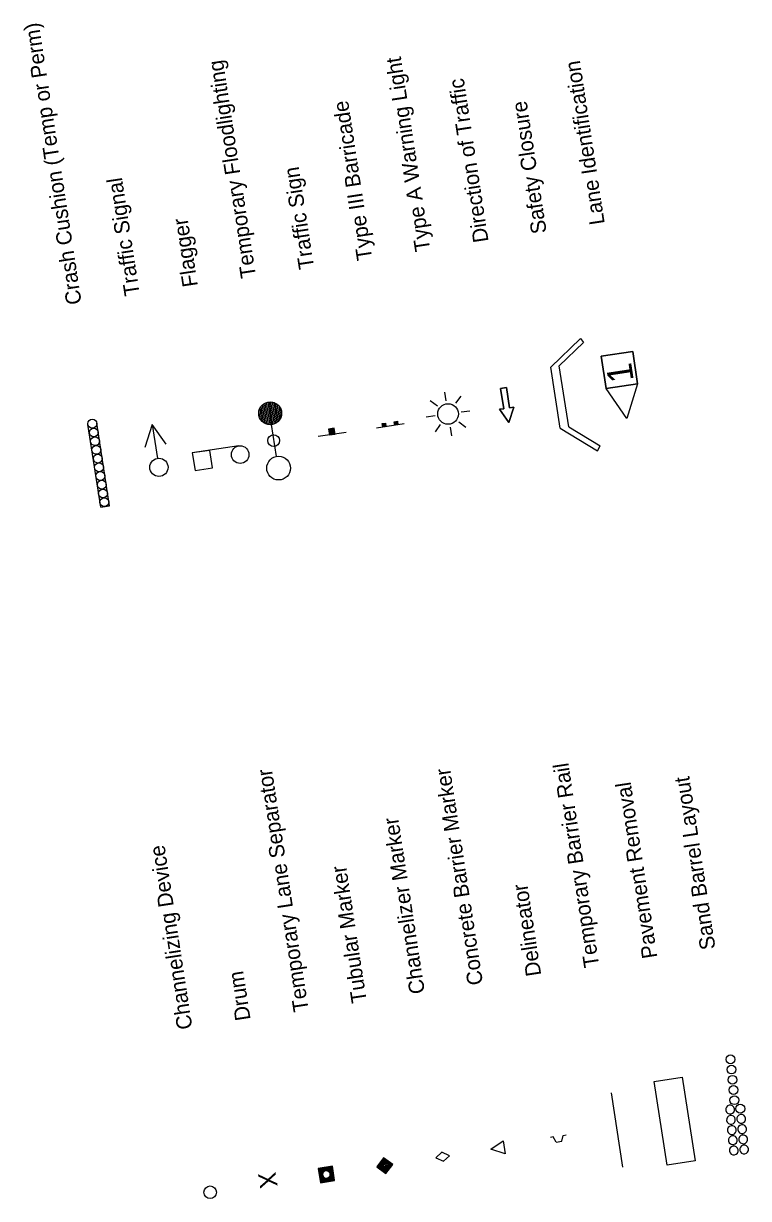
# Model space of a CAD drawing. Extents: x 5190448 to 5202667, y 3698220 to 3717523.
# Drawn here: x 5202051 to 5202667, y 3698220 to 3699220 of the extents above; entities that cross this region are included whole.
import ezdxf

# ---------------------------------------------------------------- set-up
doc = ezdxf.new("R2010")
doc.units = 0
for name, color, linetype in [('Default', 7, 'Continuous'), ('dsnCurbBack', 7, 'Continuous'), ('dsnCurbFace', 7, 'Continuous'), ('dsnIntersectionGJSLine', 7, 'Continuous'), ('dsnLaneLine', 7, 'Continuous'), ('dsnSawCutLine', 7, 'Continuous'), ('dsnShadingSpecial', 7, 'Continuous'), ('dsnShoulderPaved', 7, 'Continuous')]:
    doc.layers.add(name, color=color, linetype=linetype)

msp = doc.modelspace()

# ---------------------------------------------------------------- linework, layer by layer
at = {"layer": 'Default'}
for p, q in [((5202568.7, 3698940.8), (5202542, 3698936.8)), ((5202572.9, 3698913.3), (5202568.7, 3698940.8)), ((5202568.7, 3698940.8), (5202568.7, 3698940.8)), ((5202542, 3698936.8), (5202546.2, 3698909.3)), ((5202546.2, 3698909.3), (5202572.9, 3698913.3)), ((5202546.2, 3698909.3), (5202572.9, 3698913.3)), ((5202572.9, 3698913.3), (5202546.2, 3698909.3)), ((5202572.9, 3698913.3), (5202546.2, 3698909.3)), ((5202572.9, 3698913.3), (5202563.8, 3698883.8)), ((5202563.8, 3698883.8), (5202546.2, 3698909.3))]:
    msp.add_line(p, q, dxfattribs=at)
msp.add_lwpolyline([(5202546.2, 3698909.3), (5202542, 3698936.8), (5202568.7, 3698940.8), (5202572.9, 3698913.3)], dxfattribs=at)
at = {"layer": 'dsnCurbFace'}
for p, q in [((5202410, 3698898.7), (5202408.9, 3698906.1)), ((5202418.4, 3698896.7), (5202422.8, 3698902.7)), ((5202402.7, 3698894.3), (5202396.6, 3698898.7)), ((5202400.6, 3698885.9), (5202393.2, 3698884.8)), ((5202420.8, 3698880.9), (5202426.8, 3698876.5)), ((5202422.8, 3698889.3), (5202430.3, 3698890.4)), ((5202160.2, 3698878.5), (5202153.9, 3698859.1)), ((5202160.2, 3698878.5), (5202164.6, 3698849.8)), ((5202172, 3698861.8), (5202160.2, 3698878.5)), ((5202405.1, 3698878.5), (5202400.6, 3698872.5)), ((5202413.4, 3698876.5), (5202414.5, 3698869.1)), ((5202233.8, 3698860.4), (5202194.2, 3698854.4))]:
    msp.add_line(p, q, dxfattribs=at)
for points in [[(5202456.4, 3698909.4), (5202461.4, 3698910.2), (5202464, 3698892.9), (5202467.7, 3698893.5), (5202463.4, 3698880.2), (5202455.4, 3698891.6), (5202459.1, 3698892.1)], [(5202194.2, 3698854.4), (5202196.5, 3698839.5), (5202211.3, 3698841.8), (5202209.1, 3698856.6)]]:
    msp.add_lwpolyline(points, close=True, dxfattribs=at)
for centre, radius in [((5202411.7, 3698887.6), 8.75), ((5202234.9, 3698853), 7.5), ((5202165.8, 3698842.2), 7.74)]:
    msp.add_circle(centre, radius, dxfattribs=at)
at = {"layer": 'dsnIntersectionGJSLine'}
msp.add_lwpolyline([(5202459.1, 3698892.1), (5202455.4, 3698891.6), (5202463.4, 3698880.2), (5202467.7, 3698893.5), (5202464, 3698892.9), (5202461.4, 3698910.2), (5202456.4, 3698909.4), (5202459.1, 3698892.1)], dxfattribs=at)
at = {"layer": 'dsnLaneLine'}
for p, q in [((5202365.9, 3698880.8), (5202368.6, 3698881.2)), ((5202368.7, 3698881), (5202365.9, 3698880.6)), ((5202365.9, 3698880.5), (5202368.7, 3698880.9)), ((5202116.3, 3698808.3), (5202105.5, 3698878.7)), ((5202123.7, 3698809.4), (5202112.9, 3698879.8)), ((5202261.4, 3698878.5), (5202265.5, 3698851.4)), ((5202325, 3698871.9), (5202301.3, 3698868.3)), ((5202314.9, 3698875), (5202310.1, 3698874.3)), ((5202310.2, 3698874), (5202315, 3698874.8)), ((5202315, 3698874.6), (5202310.2, 3698873.8)), ((5202310.2, 3698873.6), (5202315.1, 3698874.3)), ((5202315.1, 3698874.1), (5202310.3, 3698873.4)), ((5202310.3, 3698873), (5202315.1, 3698873.7)), ((5202315.2, 3698873.6), (5202310.3, 3698872.8)), ((5202310.4, 3698872.4), (5202315.2, 3698873.2)), ((5202315.3, 3698872.9), (5202310.5, 3698872.1)), ((5202310.5, 3698871.8), (5202315.3, 3698872.6)), ((5202315.3, 3698872.4), (5202310.5, 3698871.7)), ((5202310.6, 3698871.4), (5202315.4, 3698872.2)), ((5202315.4, 3698871.9), (5202310.6, 3698871.1)), ((5202310.6, 3698871), (5202315.5, 3698871.7)), ((5202315.5, 3698871.5), (5202310.7, 3698870.8)), ((5202310.7, 3698870.5), (5202315.5, 3698871.3)), ((5202315.6, 3698871), (5202310.7, 3698870.3)), ((5202310.8, 3698870.1), (5202315.6, 3698870.8)), ((5202350.8, 3698875.8), (5202374.5, 3698879.4)), ((5202355.7, 3698879.2), (5202358.5, 3698879.6)), ((5202358.5, 3698879.5), (5202355.7, 3698879.1)), ((5202355.8, 3698878.9), (5202358.5, 3698879.4)), ((5202358.5, 3698879.2), (5202355.8, 3698878.8)), ((5202355.8, 3698878.7), (5202358.6, 3698879.1)), ((5202358.6, 3698878.9), (5202355.8, 3698878.5)), ((5202355.8, 3698878.4), (5202358.6, 3698878.8)), ((5202358.6, 3698878.6), (5202355.9, 3698878.1)), ((5202355.9, 3698878), (5202358.7, 3698878.4)), ((5202358.7, 3698878.2), (5202355.9, 3698877.8)), ((5202355.9, 3698877.7), (5202358.7, 3698878.1)), ((5202358.7, 3698878), (5202356, 3698877.6)), ((5202356, 3698877.4), (5202358.7, 3698877.8)), ((5202358.8, 3698877.7), (5202356, 3698877.3)), ((5202356, 3698877.2), (5202358.8, 3698877.6)), ((5202358.8, 3698877.5), (5202356, 3698877.1)), ((5202356.1, 3698876.9), (5202358.8, 3698877.3)), ((5202358.8, 3698877.2), (5202356.1, 3698876.8)), ((5202368.7, 3698880.8), (5202365.9, 3698880.3)), ((5202366, 3698880.2), (5202368.7, 3698880.7)), ((5202368.8, 3698880.4), (5202366, 3698880)), ((5202366, 3698879.9), (5202368.8, 3698880.3)), ((5202368.8, 3698880.1), (5202366, 3698879.7)), ((5202366.1, 3698879.5), (5202368.8, 3698879.9)), ((5202368.9, 3698879.8), (5202366.1, 3698879.3)), ((5202366.1, 3698879.2), (5202368.9, 3698879.7)), ((5202368.9, 3698879.5), (5202366.1, 3698879.1)), ((5202366.2, 3698878.9), (5202368.9, 3698879.4)), ((5202368.9, 3698879.3), (5202366.2, 3698878.8)), ((5202366.2, 3698878.7), (5202368.9, 3698879.2)), ((5202369, 3698879), (5202366.2, 3698878.6)), ((5202366.2, 3698878.5), (5202369, 3698878.9)), ((5202369, 3698878.8), (5202366.3, 3698878.3)), ((5202116.3, 3698808.3), (5202123.7, 3698809.4)), ((5202501.2, 3698272.2), (5202498.7, 3698271.8)), ((5202503.6, 3698267.8), (5202501.2, 3698272.2)), ((5202508.5, 3698268.6), (5202509.5, 3698273.5)), ((5202509.5, 3698273.5), (5202512, 3698273.9)), ((5202503.6, 3698267.8), (5202508.5, 3698268.6))]:
    msp.add_line(p, q, dxfattribs=at)
for points in [[(5202251.5, 3698892.1), (5202253.1, 3698881.8)], [(5202252.5, 3698893.9), (5202254.6, 3698880.4)], [(5202253.6, 3698895.2), (5202256, 3698879.6)], [(5202254.7, 3698896.1), (5202257.3, 3698879)], [(5202255.9, 3698896.8), (5202258.7, 3698878.6)], [(5202257.1, 3698897.4), (5202260, 3698878.5)], [(5202258.3, 3698897.7), (5202261.2, 3698878.5)], [(5202258.3, 3698897.7), (5202261.2, 3698878.5)], [(5202259.5, 3698897.9), (5202262.5, 3698878.7)], [(5202260.8, 3698898), (5202263.7, 3698879)], [(5202262.1, 3698897.8), (5202264.9, 3698879.6)], [(5202263.4, 3698897.5), (5202266.1, 3698880.3)], [(5202264.8, 3698896.9), (5202267.2, 3698881.2)], [(5202266.2, 3698896.1), (5202268.3, 3698882.4)], [(5202267.7, 3698894.7), (5202269.3, 3698884.1)], [(5202269.3, 3698892.2), (5202270.1, 3698887.1)], [(5202250.7, 3698888.9), (5202251.4, 3698884.6)], [(5202458.7, 3698269), (5202460.4, 3698257.8), (5202448.2, 3698261.8), (5202458.7, 3698269), (5202460.4, 3698257.8)], [(5202351.9, 3698247), (5202358.6, 3698241.8), (5202364.1, 3698248.9), (5202356.9, 3698254), (5202352.4, 3698247.3), (5202358.5, 3698242.6), (5202363.3, 3698248.8), (5202357.1, 3698253.2), (5202353.2, 3698247.4), (5202358.3, 3698243.4), (5202362.4, 3698248.8), (5202357.3, 3698252.3), (5202354.3, 3698247.6), (5202358.2, 3698244.4), (5202361.2, 3698248.6), (5202357.5, 3698251.1), (5202355.2, 3698247.7), (5202358.1, 3698245.4), (5202360, 3698248.5), (5202357.8, 3698250), (5202356.3, 3698248), (5202357.8, 3698246.5), (5202358.7, 3698248.4), (5202357.9, 3698248.8), (5202357.7, 3698247.9)], [(5202406.5, 3698259.2), (5202401.2, 3698254.5), (5202407.7, 3698251.6), (5202413, 3698256.3), (5202406.5, 3698259.2)]]:
    msp.add_lwpolyline(points, dxfattribs=at)
for points in [[(5202369, 3698878.6), (5202366.3, 3698878.2), (5202365.8, 3698881), (5202368.6, 3698881.4)], [(5202310.8, 3698869.8), (5202315.7, 3698870.5), (5202314.9, 3698875.4), (5202310.1, 3698874.6)], [(5202358.9, 3698877.1), (5202356.1, 3698876.6), (5202355.7, 3698879.4), (5202358.4, 3698879.8)], [(5202364.6, 3698248.9), (5202356.7, 3698254.6), (5202351, 3698246.8), (5202358.8, 3698241)]]:
    msp.add_lwpolyline(points, close=True, dxfattribs=at)
for centre, radius in [((5202260.4, 3698888.2), 9.75), ((5202263.4, 3698864.9), 5.04), ((5202267.6, 3698841.5), 10.1), ((5202651.9, 3698338.3), 3.75), ((5202652.7, 3698329.6), 3.75), ((5202653.6, 3698320.9), 3.75), ((5202654.4, 3698312.2), 3.75), ((5202655.2, 3698303.5), 3.75), ((5202660.2, 3698296.3), 3.75), ((5202660.2, 3698296.3), 3.75), ((5202308.3, 3698240.3), 3.3)]:
    msp.add_circle(centre, radius, dxfattribs=at)
for centre, start, end in [((5202651.5, 3698295.5), 100.2697, 280.2697), ((5202651.5, 3698295.5), 280.2697, 100.2697), ((5202661, 3698287.6), 100.2697, 280.2697), ((5202661, 3698287.6), 280.2697, 100.2697), ((5202652.3, 3698286.8), 100.2697, 280.2697), ((5202653.1, 3698278.1), 100.2697, 280.2697), ((5202652.3, 3698286.8), 280.2697, 100.2697), ((5202653.1, 3698278.1), 280.2697, 100.2697), ((5202661.8, 3698278.9), 100.2697, 280.2697), ((5202661.8, 3698278.9), 280.2697, 100.2697), ((5202653.9, 3698269.4), 100.2697, 280.2697), ((5202653.9, 3698269.4), 280.2697, 100.2697), ((5202662.6, 3698270.2), 100.2697, 280.2697), ((5202662.6, 3698270.2), 280.2697, 100.2697), ((5202654.7, 3698260.7), 100.2697, 280.2697), ((5202654.7, 3698260.7), 280.2697, 100.2697), ((5202663.4, 3698261.5), 100.2697, 280.2697), ((5202663.4, 3698261.5), 280.2697, 100.2697)]:
    msp.add_arc(centre, 3.75, start, end, dxfattribs=at)
at = {"layer": 'dsnSawCutLine'}
for p, q in [((5202597.9, 3698248.3), (5202587.1, 3698319.4)), ((5202621.7, 3698251.9), (5202597.9, 3698248.3))]:
    msp.add_line(p, q, dxfattribs=at)
msp.add_lwpolyline([(5202587.1, 3698319.4), (5202610.8, 3698323.1), (5202621.7, 3698251.9)], dxfattribs=at)
at = {"layer": 'dsnShadingSpecial'}
for p, q in [((5202499, 3698927.5), (5202524.2, 3698951.8)), ((5202524.2, 3698951.8), (5202526.9, 3698948.5)), ((5202506.3, 3698928.6), (5202526.9, 3698948.5)), ((5202506.9, 3698875.6), (5202499, 3698927.5)), ((5202514.3, 3698876.7), (5202506.3, 3698928.6)), ((5202506.9, 3698875.6), (5202538.7, 3698856.3)), ((5202514.3, 3698876.7), (5202541, 3698860.4)), ((5202538.7, 3698856.3), (5202541, 3698860.4))]:
    msp.add_line(p, q, dxfattribs=at)
for points in [[(5202315.2, 3698235.2), (5202313.4, 3698247.3), (5202301.3, 3698245.4), (5202303.1, 3698233.3), (5202315.2, 3698235.2)], [(5202315.2, 3698235.2), (5202313.4, 3698247.3), (5202301.3, 3698245.4), (5202303.1, 3698233.3), (5202315.2, 3698235.2)], [(5202315.2, 3698235.2), (5202313.4, 3698247.3), (5202301.3, 3698245.4), (5202303.1, 3698233.4), (5202315.2, 3698235.2)], [(5202315.1, 3698235.4), (5202313.3, 3698247.2), (5202301.4, 3698245.4), (5202303.2, 3698233.4), (5202315.2, 3698235.3)], [(5202315, 3698235.5), (5202313.3, 3698247.1), (5202301.4, 3698245.3), (5202303.2, 3698233.5), (5202315.2, 3698235.3)], [(5202315, 3698235.6), (5202313.2, 3698247.1), (5202301.5, 3698245.3), (5202303.3, 3698233.6), (5202315.2, 3698235.4)], [(5202314.9, 3698235.6), (5202313.2, 3698247), (5202301.6, 3698245.2), (5202303.4, 3698233.7), (5202315.1, 3698235.4)], [(5202314.8, 3698235.7), (5202313.1, 3698246.9), (5202301.7, 3698245.2), (5202303.4, 3698233.7), (5202315, 3698235.5)], [(5202314.7, 3698235.7), (5202313, 3698246.8), (5202301.7, 3698245.1), (5202303.5, 3698233.8), (5202315, 3698235.6)], [(5202314.7, 3698235.8), (5202313, 3698246.8), (5202301.8, 3698245.1), (5202303.5, 3698233.9), (5202314.9, 3698235.6)], [(5202314.6, 3698235.8), (5202312.9, 3698246.7), (5202301.9, 3698245), (5202303.6, 3698234), (5202314.8, 3698235.7)], [(5202314.5, 3698235.9), (5202312.9, 3698246.6), (5202302, 3698244.9), (5202303.6, 3698234), (5202314.7, 3698235.7)], [(5202314.4, 3698235.9), (5202312.8, 3698246.5), (5202302, 3698244.9), (5202303.7, 3698234.1), (5202314.7, 3698235.8)], [(5202314.4, 3698236), (5202312.8, 3698246.5), (5202302.1, 3698244.8), (5202303.7, 3698234.2), (5202314.6, 3698235.8)], [(5202314.3, 3698236.1), (5202312.7, 3698246.4), (5202302.2, 3698244.8), (5202303.8, 3698234.3), (5202314.5, 3698235.9)], [(5202314.2, 3698236.1), (5202312.7, 3698246.3), (5202302.3, 3698244.7), (5202303.9, 3698234.3), (5202314.4, 3698235.9)], [(5202314.1, 3698236.2), (5202312.6, 3698246.2), (5202302.3, 3698244.7), (5202303.9, 3698234.4), (5202314.4, 3698236)], [(5202314.1, 3698236.2), (5202312.5, 3698246.2), (5202302.4, 3698244.6), (5202304, 3698234.5), (5202314.3, 3698236.1)], [(5202314, 3698236.3), (5202312.5, 3698246.1), (5202302.5, 3698244.6), (5202304, 3698234.6), (5202314.2, 3698236.1)], [(5202313.9, 3698236.3), (5202312.4, 3698246), (5202302.6, 3698244.5), (5202304.1, 3698234.6), (5202314.1, 3698236.2)], [(5202313.8, 3698236.4), (5202312.4, 3698245.9), (5202302.6, 3698244.4), (5202304.1, 3698234.7), (5202314.1, 3698236.2)], [(5202313.8, 3698236.4), (5202312.3, 3698245.9), (5202302.7, 3698244.4), (5202304.2, 3698234.8), (5202314, 3698236.3)], [(5202313.7, 3698236.5), (5202312.3, 3698245.8), (5202302.8, 3698244.3), (5202304.2, 3698234.9), (5202313.9, 3698236.3)], [(5202313.6, 3698236.6), (5202312.2, 3698245.7), (5202302.9, 3698244.3), (5202304.3, 3698234.9), (5202313.8, 3698236.4)], [(5202313.5, 3698236.6), (5202312.2, 3698245.6), (5202302.9, 3698244.2), (5202304.3, 3698235), (5202313.8, 3698236.4)], [(5202313.5, 3698236.7), (5202312.1, 3698245.6), (5202303, 3698244.2), (5202304.4, 3698235.1), (5202313.7, 3698236.5)], [(5202313.4, 3698236.7), (5202312, 3698245.5), (5202303.1, 3698244.1), (5202304.5, 3698235.2), (5202313.6, 3698236.6)], [(5202313.3, 3698236.8), (5202312, 3698245.4), (5202303.2, 3698244.1), (5202304.5, 3698235.2), (5202313.5, 3698236.6)], [(5202313.2, 3698236.8), (5202311.9, 3698245.3), (5202303.2, 3698244), (5202304.6, 3698235.3), (5202313.5, 3698236.7)], [(5202313.2, 3698236.9), (5202311.9, 3698245.3), (5202303.3, 3698243.9), (5202304.6, 3698235.4), (5202313.4, 3698236.7)], [(5202313.1, 3698236.9), (5202311.8, 3698245.2), (5202303.4, 3698243.9), (5202304.7, 3698235.5), (5202313.3, 3698236.8)], [(5202313, 3698237), (5202311.8, 3698245.1), (5202303.5, 3698243.8), (5202304.7, 3698235.5), (5202313.2, 3698236.8)], [(5202312.9, 3698237.1), (5202311.7, 3698245), (5202303.5, 3698243.8), (5202304.8, 3698235.6), (5202313.2, 3698236.9)], [(5202312.9, 3698237.1), (5202311.7, 3698245), (5202303.6, 3698243.7), (5202304.8, 3698235.7), (5202313.1, 3698236.9)], [(5202312.8, 3698237.2), (5202311.6, 3698244.9), (5202303.7, 3698243.7), (5202304.9, 3698235.8), (5202313, 3698237)], [(5202312.7, 3698237.2), (5202311.5, 3698244.8), (5202303.8, 3698243.6), (5202305, 3698235.8), (5202312.9, 3698237.1)], [(5202312.6, 3698237.3), (5202311.5, 3698244.7), (5202303.8, 3698243.6), (5202305, 3698235.9), (5202312.9, 3698237.1)], [(5202312.6, 3698237.3), (5202311.4, 3698244.7), (5202303.9, 3698243.5), (5202305.1, 3698236), (5202312.8, 3698237.2)], [(5202312.5, 3698237.4), (5202311.4, 3698244.6), (5202304, 3698243.4), (5202305.1, 3698236.1), (5202312.7, 3698237.2)], [(5202312.4, 3698237.4), (5202311.3, 3698244.5), (5202304.1, 3698243.4), (5202305.2, 3698236.1), (5202312.6, 3698237.3)], [(5202312.3, 3698237.5), (5202311.3, 3698244.4), (5202304.1, 3698243.3), (5202305.2, 3698236.2), (5202312.6, 3698237.3)], [(5202312.3, 3698237.6), (5202311.2, 3698244.4), (5202304.2, 3698243.3), (5202305.3, 3698236.3), (5202312.5, 3698237.4)], [(5202312.2, 3698237.6), (5202311.2, 3698244.3), (5202304.3, 3698243.2), (5202305.3, 3698236.4), (5202312.4, 3698237.4)], [(5202312.1, 3698237.7), (5202311.1, 3698244.2), (5202304.4, 3698243.2), (5202305.4, 3698236.4), (5202312.3, 3698237.5)], [(5202312, 3698237.7), (5202311.1, 3698244.1), (5202304.4, 3698243.1), (5202305.5, 3698236.5), (5202312.3, 3698237.6)], [(5202312, 3698237.8), (5202311, 3698244), (5202304.5, 3698243.1), (5202305.5, 3698236.6), (5202312.2, 3698237.6)], [(5202307.2, 3698243.4), (5202304.6, 3698243), (5202305, 3698240.4)], [(5202306.9, 3698243.3), (5202304.7, 3698243), (5202305, 3698240.7)], [(5202306.7, 3698243.2), (5202304.7, 3698242.9), (5202305, 3698240.9)], [(5202306.5, 3698243.1), (5202304.8, 3698242.8), (5202305.1, 3698241.1)], [(5202306.4, 3698243), (5202304.9, 3698242.8), (5202305.1, 3698241.3)], [(5202306.3, 3698242.9), (5202305, 3698242.7), (5202305.2, 3698241.4)], [(5202306.2, 3698242.8), (5202305, 3698242.7), (5202305.2, 3698241.5)], [(5202306.1, 3698242.8), (5202305.1, 3698242.6), (5202305.3, 3698241.7)], [(5202306, 3698242.7), (5202305.2, 3698242.6), (5202305.3, 3698241.8)], [(5202305.9, 3698242.6), (5202305.3, 3698242.5), (5202305.4, 3698241.9)], [(5202305.8, 3698242.5), (5202305.3, 3698242.5), (5202305.4, 3698242)], [(5202305.8, 3698242.5), (5202305.4, 3698242.4), (5202305.5, 3698242)], [(5202305.7, 3698242.4), (5202305.5, 3698242.3), (5202305.5, 3698242.1)], [(5202305.7, 3698242.3), (5202305.6, 3698242.3), (5202305.6, 3698242.2)], [(5202311.3, 3698241.4), (5202310.9, 3698244), (5202308.4, 3698243.6)], [(5202311.2, 3698241.7), (5202310.9, 3698243.9), (5202308.7, 3698243.6)], [(5202311.1, 3698241.9), (5202310.8, 3698243.8), (5202308.9, 3698243.5)], [(5202311, 3698242), (5202310.8, 3698243.7), (5202309.1, 3698243.5)], [(5202310.9, 3698242.2), (5202310.7, 3698243.7), (5202309.2, 3698243.4)], [(5202310.9, 3698242.3), (5202310.7, 3698243.6), (5202309.3, 3698243.4)], [(5202310.8, 3698242.4), (5202310.6, 3698243.5), (5202309.5, 3698243.3)], [(5202310.7, 3698242.5), (5202310.6, 3698243.4), (5202309.6, 3698243.3)], [(5202310.6, 3698242.6), (5202310.5, 3698243.4), (5202309.7, 3698243.2)], [(5202310.5, 3698242.6), (5202310.4, 3698243.3), (5202309.8, 3698243.2)], [(5202310.5, 3698242.7), (5202310.4, 3698243.2), (5202309.9, 3698243.1)], [(5202310.4, 3698242.8), (5202310.3, 3698243.1), (5202310, 3698243.1)], [(5202310.3, 3698242.9), (5202310.3, 3698243.1), (5202310.1, 3698243)], [(5202310.2, 3698242.9), (5202310.2, 3698243), (5202310.1, 3698243)], [(5202305.2, 3698239.2), (5202305.6, 3698236.7), (5202308.1, 3698237.1)], [(5202305.3, 3698239), (5202305.6, 3698236.7), (5202307.8, 3698237.1)], [(5202305.4, 3698238.8), (5202305.7, 3698236.8), (5202307.6, 3698237.1)], [(5202305.5, 3698238.6), (5202305.7, 3698236.9), (5202307.5, 3698237.2)], [(5202305.6, 3698238.5), (5202305.8, 3698237), (5202307.3, 3698237.2)], [(5202305.6, 3698238.4), (5202305.8, 3698237), (5202307.2, 3698237.2)], [(5202305.7, 3698238.3), (5202305.9, 3698237.1), (5202307, 3698237.3)], [(5202305.8, 3698238.2), (5202306, 3698237.2), (5202306.9, 3698237.3)], [(5202305.9, 3698238.1), (5202306, 3698237.3), (5202306.8, 3698237.4)], [(5202306, 3698238), (5202306.1, 3698237.3), (5202306.7, 3698237.4)], [(5202306, 3698237.9), (5202306.1, 3698237.4), (5202306.6, 3698237.5)], [(5202306.1, 3698237.8), (5202306.2, 3698237.5), (5202306.5, 3698237.5)], [(5202306.2, 3698237.8), (5202306.2, 3698237.6), (5202306.4, 3698237.6)], [(5202306.3, 3698237.7), (5202306.3, 3698237.6), (5202306.4, 3698237.7)], [(5202309.3, 3698237.2), (5202312.1, 3698237.7)], [(5202309.6, 3698237.3), (5202312, 3698237.7)], [(5202309.8, 3698237.4), (5202312, 3698237.8)], [(5202310, 3698237.5), (5202311.9, 3698237.8)], [(5202310.1, 3698237.6), (5202311.8, 3698237.9)], [(5202310.2, 3698237.7), (5202311.7, 3698237.9)], [(5202310.3, 3698237.8), (5202311.7, 3698238)], [(5202310.4, 3698237.9), (5202311.6, 3698238)], [(5202310.5, 3698238), (5202311.5, 3698238.1)], [(5202310.6, 3698238), (5202311.4, 3698238.2)], [(5202310.7, 3698238.2), (5202311.3, 3698238.3)], [(5202310.7, 3698238.1), (5202311.4, 3698238.2)], [(5202310.8, 3698238.3), (5202311.2, 3698238.3)], [(5202310.9, 3698238.3), (5202311.1, 3698238.4)], [(5202311.2, 3698238.3), (5202311.1, 3698238.8)], [(5202311.1, 3698238.4), (5202311.1, 3698238.7)], [(5202311.4, 3698238.2), (5202311.2, 3698239)], [(5202311.3, 3698238.3), (5202311.2, 3698238.9)], [(5202311.5, 3698238.1), (5202311.3, 3698239.2)], [(5202311.4, 3698238.2), (5202311.3, 3698239.1)], [(5202311.7, 3698238), (5202311.4, 3698239.5)], [(5202311.6, 3698238), (5202311.4, 3698239.4)], [(5202311.9, 3698237.8), (5202311.5, 3698240.2)], [(5202311.8, 3698237.9), (5202311.5, 3698239.9)], [(5202311.7, 3698237.9), (5202311.5, 3698239.7)]]:
    msp.add_lwpolyline(points, dxfattribs=at)
for centre in [(5202109.2, 3698879.3), (5202110.4, 3698871.8), (5202111.5, 3698864.4), (5202112.6, 3698857), (5202113.8, 3698849.6), (5202114.9, 3698842.2), (5202116, 3698834.8), (5202117.2, 3698827.4), (5202118.3, 3698819.9), (5202119.4, 3698812.5)]:
    msp.add_circle(centre, 3.75, dxfattribs=at)
at = {"layer": 'dsnShoulderPaved'}
msp.add_line((5202560.2, 3698246.4), (5202550.6, 3698309.7), dxfattribs=at)
msp.add_circle((5202209.4, 3698225.2), 5.37, dxfattribs=at)
msp.add_circle((5202209.4, 3698225.2), 5.37, dxfattribs=at)

# ---------------------------------------------------------------- texts
at = {"layer": 'Default'}
msp.add_text('1', height=21.6, rotation=98.6853, dxfattribs=at).set_placement((5202569.7, 3698916.2))
at = {"layer": 'dsnCurbBack'}
for s, p in [('Crash Cushion (Temp or Perm)', (5202100.2, 3698981.6)), ('Type A Warning Light', (5202396.7, 3699026.9)), ('Temporary Floodlighting', (5202248.5, 3699004.3)), ('Lane Identification', (5202545, 3699049.6)), ('Direction of Traffic', (5202446.2, 3699034.5)), ('Type III Barricade', (5202347.3, 3699019.4)), ('Safety Closure', (5202495.6, 3699042)), ('Traffic Sign', (5202297.9, 3699011.8)), ('Traffic Signal', (5202149.6, 3698989.2)), ('Flagger', (5202199, 3698996.7)), ('Temporary Lane Separator', (5202293.3, 3698379.8)), ('Concrete Barrier Marker', (5202441.5, 3698402.4)), ('Temporary Barrier Rail', (5202540.4, 3698417.5)), ('Pavement Removal', (5202589.8, 3698425.1)), ('Sand Barrel Layout', (5202639.2, 3698432.6)), ('Channelizer Marker', (5202392.1, 3698394.9)), ('Channelizing Device', (5202194.4, 3698364.7)), ('Tubular Marker', (5202342.7, 3698387.3)), ('Delineator', (5202491, 3698410)), ('Drum', (5202243.8, 3698372.2))]:
    msp.add_text(s, height=13, rotation=98.6831, dxfattribs=at).set_placement(p)
at = {"layer": 'dsnShoulderPaved'}
msp.add_text('X', height=15, rotation=278.6831, dxfattribs=at).set_placement((5202250, 3698241))

doc.saveas('drawing.dxf')
